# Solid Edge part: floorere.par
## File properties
Author: Deepak Maini
Template: normal.par
Last saved by: Robert a Rhodes jr
Revision: 5
Application: Solid Edge
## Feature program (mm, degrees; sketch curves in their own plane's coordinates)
sketch for "unnamed Protrusion 1" plane through (0, 0, 18.8714) normal (0, 0, 1) x-axis (1, 0, 0)
  line (-106.7153, 22.606) -> (-36.8209, 22.606)
  arc centre (-20.2938, 18.624) radius 17 from (-36.8209, 22.606) to (-36.6443, 13.97) cw
  line (-36.6443, 13.97) -> (-106.7153, 13.97)
  line (-106.7153, 13.97) -> (-106.7153, 22.606)
extrude "unnamed Protrusion 1" add finite 8.5604 along +normal
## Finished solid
Body 1: solid body, 6 faces, 12 edges, 8 vertices.
  Faces by surface: plane 5, cylinder 1
  Edges by curve: line 10, circle 2
Bounding box of the edges (mm): 103.421 x 34.000 x 8.560, from (-106.7153, 1.624, 18.8714) to (-3.2938, 35.624, 27.4319).
Cylindrical faces by radius (mm): R17 x1
Planar faces by outward normal: +y 1, +z 1, -x 1, -y 1, -z 1
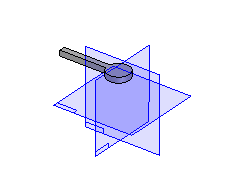
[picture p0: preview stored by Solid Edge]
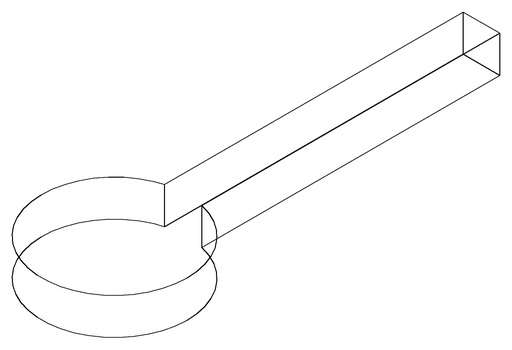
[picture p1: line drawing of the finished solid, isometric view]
